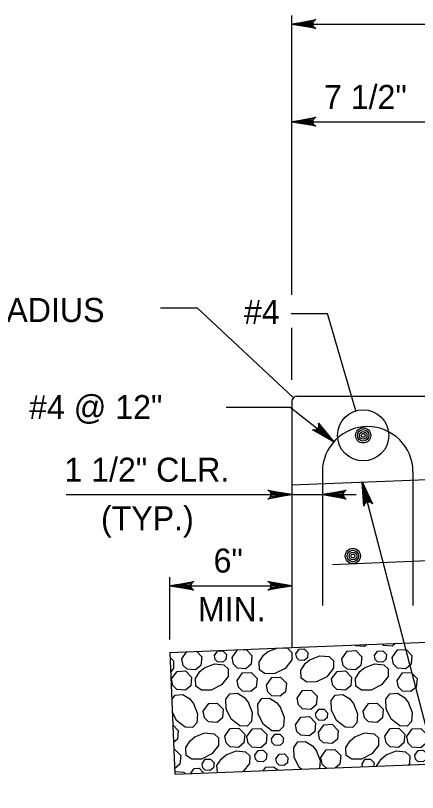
# Model space of a CAD drawing. Extents: x 2084213 to 2099800, y 976677 to 981262.
# Drawn here: x 2095066.5 to 2095231.3, y 976944.9 to 977263.3 of the extents above; entities that cross this region are included whole.
import ezdxf

# ---------------------------------------------------------------- set-up
doc = ezdxf.new("R2010")
doc.units = 0
doc.layers.add('1', color=7, linetype='Continuous')

msp = doc.modelspace()

# ---------------------------------------------------------------- linework, layer by layer
at = {"layer": '1'}
for p, q in [((2095179.78, 977148.81), (2095179.78, 977263.26)), ((2095179.78, 977259.75), (2095246.45, 977259.75)), ((2095179.78, 977219.75), (2095293.16, 977219.75)), ((2095126, 977143.47), (2095140.93, 977143.47)), ((2095180.39, 977106.67), (2095140.93, 977143.47)), ((2095179.48, 977141.19), (2095194.42, 977141.19)), ((2095206.05, 977101.32), (2095194.42, 977141.19)), ((2095179.78, 977114.01), (2095179.78, 977135.31)), ((2095181.86, 977107.28), (2095236.37, 977107.28)), ((2095179.78, 977105.2), (2095179.78, 977004.35)), ((2095152.83, 977102.87), (2095178.95, 977102.87)), ((2095196.94, 977088.58), (2095178.95, 977102.87)), ((2095209, 977091.25), (2095209, 977091.25)), ((2095192.28, 977076.28), (2095192.28, 977021.52)), ((2095229.4, 977076.27), (2095229.4, 977021.51)), ((2095179.78, 977071), (2095246.45, 977073.67)), ((2095244.96, 976932.65), (2095208.54, 977072.16)), ((2095087.34, 977067.01), (2095206.14, 977067.01)), ((2095196.45, 977038.38), (2095404.32, 977046.69)), ((2095129.82, 977007.59), (2095129.82, 977033.16)), ((2095129.82, 977029.61), (2095179.78, 977029.61)), ((2095179.78, 977004.35), (2095404.32, 977013.33)), ((2095129.82, 977002.35), (2095179.78, 977004.35)), ((2095129.82, 977002.35), (2095131.82, 976952.39)), ((2095131.82, 976952.39), (2095404.32, 976963.29))]:
    msp.add_line(p, q, dxfattribs=at)
for points in [[(2095179.78, 977259.75), (2095189.56, 977261.58), (2095189.19, 977261.32), (2095188.81, 977261.06), (2095188.62, 977260.73), (2095188.42, 977260.4), (2095188.36, 977260.07), (2095188.31, 977259.75), (2095188.36, 977259.42), (2095188.42, 977259.09), (2095188.62, 977258.76), (2095188.81, 977258.43), (2095189.19, 977258.17), (2095189.56, 977257.91), (2095179.78, 977259.75), (2095189.19, 977258.17), (2095188.81, 977258.43), (2095179.78, 977259.75), (2095188.62, 977258.76), (2095188.42, 977259.09), (2095179.78, 977259.75), (2095188.36, 977259.42), (2095188.31, 977259.75), (2095179.78, 977259.75), (2095188.36, 977260.07), (2095188.42, 977260.4), (2095179.78, 977259.75), (2095188.62, 977260.73), (2095188.81, 977261.06), (2095179.78, 977259.75), (2095189.19, 977261.32)], [(2095179.78, 977219.75), (2095189.56, 977221.58), (2095189.19, 977221.32), (2095188.81, 977221.06), (2095188.62, 977220.73), (2095188.42, 977220.4), (2095188.36, 977220.07), (2095188.31, 977219.75), (2095188.36, 977219.42), (2095188.42, 977219.09), (2095188.62, 977218.76), (2095188.81, 977218.43), (2095189.19, 977218.17), (2095189.56, 977217.91), (2095179.78, 977219.75), (2095189.19, 977218.17), (2095188.81, 977218.43), (2095179.78, 977219.75), (2095188.62, 977218.76), (2095188.42, 977219.09), (2095179.78, 977219.75), (2095188.36, 977219.42), (2095188.31, 977219.75), (2095179.78, 977219.75), (2095188.36, 977220.07), (2095188.42, 977220.4), (2095179.78, 977219.75), (2095188.62, 977220.73), (2095188.81, 977221.06), (2095179.78, 977219.75), (2095189.19, 977221.32)], [(2095196.94, 977088.58), (2095188.29, 977093.5), (2095188.74, 977093.46), (2095189.2, 977093.41), (2095189.56, 977093.54), (2095189.92, 977093.66), (2095190.17, 977093.88), (2095190.43, 977094.09), (2095190.6, 977094.38), (2095190.77, 977094.67), (2095190.83, 977095.04), (2095190.89, 977095.42), (2095190.77, 977095.86), (2095190.65, 977096.3), (2095196.94, 977088.58), (2095190.77, 977095.86), (2095190.89, 977095.42), (2095196.94, 977088.58), (2095190.83, 977095.04), (2095190.77, 977094.67), (2095196.94, 977088.58), (2095190.6, 977094.38), (2095190.43, 977094.09), (2095196.94, 977088.58), (2095190.17, 977093.88), (2095189.92, 977093.66), (2095196.94, 977088.58), (2095189.56, 977093.54), (2095189.2, 977093.41), (2095196.94, 977088.58), (2095188.74, 977093.46)], [(2095208.54, 977072.16), (2095212.79, 977063.15), (2095212.44, 977063.45), (2095212.09, 977063.75), (2095211.72, 977063.85), (2095211.36, 977063.96), (2095211.03, 977063.93), (2095210.69, 977063.9), (2095210.39, 977063.76), (2095210.09, 977063.63), (2095209.82, 977063.36), (2095209.55, 977063.09), (2095209.39, 977062.65), (2095209.24, 977062.22), (2095208.54, 977072.16), (2095209.39, 977062.65), (2095209.55, 977063.09), (2095208.54, 977072.16), (2095209.82, 977063.36), (2095210.09, 977063.63), (2095208.54, 977072.16), (2095210.39, 977063.76), (2095210.69, 977063.9), (2095208.54, 977072.16), (2095211.03, 977063.93), (2095211.36, 977063.96), (2095208.54, 977072.16), (2095211.72, 977063.85), (2095212.09, 977063.75), (2095208.54, 977072.16), (2095212.44, 977063.45)], [(2095179.78, 977067.01), (2095169.99, 977065.17), (2095170.37, 977065.43), (2095170.75, 977065.7), (2095170.94, 977066.02), (2095171.14, 977066.35), (2095171.19, 977066.68), (2095171.25, 977067.01), (2095171.19, 977067.34), (2095171.14, 977067.66), (2095170.94, 977067.99), (2095170.75, 977068.32), (2095170.37, 977068.58), (2095169.99, 977068.84), (2095179.78, 977067.01), (2095170.37, 977068.58), (2095170.75, 977068.32), (2095179.78, 977067.01), (2095170.94, 977067.99), (2095171.14, 977067.66), (2095179.78, 977067.01), (2095171.19, 977067.34), (2095171.25, 977067.01), (2095179.78, 977067.01), (2095171.19, 977066.68), (2095171.14, 977066.35), (2095179.78, 977067.01), (2095170.94, 977066.02), (2095170.75, 977065.7), (2095179.78, 977067.01), (2095170.37, 977065.43)], [(2095192.28, 977067.01), (2095202.06, 977068.84), (2095201.69, 977068.58), (2095201.31, 977068.32), (2095201.12, 977067.99), (2095200.92, 977067.66), (2095200.86, 977067.34), (2095200.81, 977067.01), (2095200.86, 977066.68), (2095200.92, 977066.35), (2095201.12, 977066.02), (2095201.31, 977065.7), (2095201.69, 977065.43), (2095202.06, 977065.17), (2095192.28, 977067.01), (2095201.69, 977065.43), (2095201.31, 977065.7), (2095192.28, 977067.01), (2095201.12, 977066.02), (2095200.92, 977066.35), (2095192.28, 977067.01), (2095200.86, 977066.68), (2095200.81, 977067.01), (2095192.28, 977067.01), (2095200.86, 977067.34), (2095200.92, 977067.66), (2095192.28, 977067.01), (2095201.12, 977067.99), (2095201.31, 977068.32), (2095192.28, 977067.01), (2095201.69, 977068.58)], [(2095129.82, 977029.61), (2095139.6, 977031.44), (2095139.23, 977031.18), (2095138.85, 977030.92), (2095138.66, 977030.59), (2095138.46, 977030.26), (2095138.4, 977029.93), (2095138.35, 977029.61), (2095138.4, 977029.28), (2095138.46, 977028.95), (2095138.66, 977028.62), (2095138.85, 977028.29), (2095139.23, 977028.03), (2095139.6, 977027.77), (2095129.82, 977029.61), (2095139.23, 977028.03), (2095138.85, 977028.29), (2095129.82, 977029.61), (2095138.66, 977028.62), (2095138.46, 977028.95), (2095129.82, 977029.61), (2095138.4, 977029.28), (2095138.35, 977029.61), (2095129.82, 977029.61), (2095138.4, 977029.93), (2095138.46, 977030.26), (2095129.82, 977029.61), (2095138.66, 977030.59), (2095138.85, 977030.92), (2095129.82, 977029.61), (2095139.23, 977031.18)], [(2095179.78, 977029.61), (2095169.99, 977027.77), (2095170.37, 977028.03), (2095170.75, 977028.29), (2095170.94, 977028.62), (2095171.14, 977028.95), (2095171.19, 977029.28), (2095171.25, 977029.61), (2095171.19, 977029.93), (2095171.14, 977030.26), (2095170.94, 977030.59), (2095170.75, 977030.92), (2095170.37, 977031.18), (2095169.99, 977031.44), (2095179.78, 977029.61), (2095170.37, 977031.18), (2095170.75, 977030.92), (2095179.78, 977029.61), (2095170.94, 977030.59), (2095171.14, 977030.26), (2095179.78, 977029.61), (2095171.19, 977029.93), (2095171.25, 977029.61), (2095179.78, 977029.61), (2095171.19, 977029.28), (2095171.14, 977028.95), (2095179.78, 977029.61), (2095170.94, 977028.62), (2095170.75, 977028.29), (2095179.78, 977029.61), (2095170.37, 977028.03)], [(2095210.51, 977005.58), (2095209.49, 977004.73), (2095206.01, 977004.98), (2095205.6, 977005.38)], [(2095222.3, 977006.05), (2095220.87, 977004.86), (2095217.39, 977005.11), (2095216.66, 977005.83)], [(2095140.65, 977002.79), (2095142.82, 977000.53), (2095142.47, 976996.97), (2095140.3, 976995.17), (2095136.82, 976995.42), (2095135.18, 976997), (2095134.65, 976999.73)], [(2095134.65, 976999.73), (2095136.69, 977002.63)], [(2095148.03, 977001.02), (2095149.36, 977002.9), (2095151.47, 977003.02), (2095152.94, 977001.5), (2095152.72, 976999.37), (2095151.42, 976998.28), (2095149.33, 976998.43), (2095148.35, 976999.38), (2095148.03, 977001.02)], [(2095155.26, 977000.21), (2095157.47, 977003.35), (2095160.99, 977003.55), (2095163.43, 977001.01), (2095163.08, 976997.45), (2095160.91, 976995.64), (2095157.43, 976995.89), (2095155.79, 976997.48), (2095155.26, 977000.21)], [(2095175.96, 977004.2), (2095177.98, 977004.03), (2095179.78, 977002.31), (2095179.72, 976999.24), (2095176.99, 976995.74), (2095172.76, 976993.63), (2095168.78, 976993.56), (2095166.54, 976995.15), (2095166.33, 976998.32), (2095168.14, 977001.16), (2095170.23, 977002.82)], [(2095170.06, 977002.72), (2095173.56, 977004.1)], [(2095181.45, 977001.75), (2095182.77, 977003.63), (2095184.88, 977003.75), (2095186.35, 977002.23), (2095186.14, 977000.09), (2095184.83, 976999.01), (2095182.75, 976999.16), (2095181.76, 977000.11), (2095181.45, 977001.75)], [(2095200.23, 976999.73), (2095202.43, 977002.87), (2095205.95, 977003.07), (2095208.4, 977000.53), (2095208.05, 976996.97), (2095205.87, 976995.17), (2095202.4, 976995.42), (2095200.76, 976997), (2095200.23, 976999.73)], [(2095213.61, 977001.02), (2095214.93, 977002.9), (2095217.05, 977003.02), (2095218.52, 977001.5), (2095218.3, 976999.37), (2095217, 976998.28), (2095214.91, 976998.43), (2095213.93, 976999.38), (2095213.61, 977001.02)], [(2095220.84, 977000.21), (2095223.04, 977003.35), (2095226.57, 977003.55), (2095229.01, 977001.01), (2095228.66, 976997.45), (2095226.48, 976995.64), (2095223.01, 976995.89), (2095221.37, 976997.48), (2095220.84, 977000.21)], [(2095129.9, 977000.25), (2095131.3, 976998.93), (2095131.24, 976995.85), (2095130.14, 976994.43)], [(2095187.16, 976999.33), (2095191.29, 977000.96), (2095195.08, 977000.64), (2095196.88, 976998.93), (2095196.82, 976995.85), (2095194.09, 976992.35), (2095189.86, 976990.24), (2095185.88, 976990.17), (2095183.64, 976991.76), (2095183.42, 976994.94), (2095185.24, 976997.77), (2095187.33, 976999.44)], [(2095144, 976995.99), (2095148.12, 976997.63), (2095151.91, 976997.3), (2095153.72, 976995.59), (2095153.66, 976992.51), (2095150.92, 976989.02), (2095146.7, 976986.91), (2095142.72, 976986.84), (2095140.47, 976988.43), (2095140.26, 976991.6), (2095142.08, 976994.44), (2095144.16, 976996.1)], [(2095209.58, 976995.99), (2095213.7, 976997.63), (2095217.49, 976997.3), (2095219.29, 976995.59), (2095219.24, 976992.51), (2095216.5, 976989.02), (2095212.28, 976986.91), (2095208.3, 976986.84), (2095206.05, 976988.43), (2095205.84, 976991.6), (2095207.66, 976994.44), (2095209.74, 976996.1)], [(2095130.5, 976991.43), (2095132.7, 976994.57), (2095136.23, 976994.77), (2095138.67, 976992.23), (2095138.32, 976988.67), (2095136.14, 976986.86), (2095132.67, 976987.12), (2095131.03, 976988.7), (2095130.5, 976991.43)], [(2095157.34, 976990.81), (2095159.54, 976993.95), (2095163.06, 976994.15), (2095165.51, 976991.62), (2095165.16, 976988.06), (2095162.98, 976986.25), (2095159.5, 976986.5), (2095157.87, 976988.09), (2095157.34, 976990.81)], [(2095169.39, 976988.89), (2095171.6, 976992.03), (2095175.12, 976992.23), (2095177.57, 976989.69), (2095177.21, 976986.14), (2095175.04, 976984.33), (2095171.56, 976984.58), (2095169.93, 976986.17), (2095169.4, 976988.89)], [(2095196.08, 976991.43), (2095198.28, 976994.57), (2095201.8, 976994.77), (2095204.25, 976992.23), (2095203.9, 976988.67), (2095201.72, 976986.86), (2095198.25, 976987.12), (2095196.61, 976988.7), (2095196.08, 976991.43)], [(2095222.91, 976990.81), (2095225.12, 976993.95), (2095228.64, 976994.15), (2095231.09, 976991.62), (2095230.73, 976988.06), (2095228.56, 976986.25), (2095225.08, 976986.5), (2095223.45, 976988.09), (2095222.92, 976990.81)], [(2095181.93, 976983.56), (2095184.14, 976986.7), (2095187.66, 976986.9), (2095190.11, 976984.36), (2095189.76, 976980.8), (2095187.58, 976978.99), (2095184.1, 976979.24), (2095182.47, 976980.83), (2095181.94, 976983.56)], [(2095130.59, 976982.97), (2095131.94, 976984.87), (2095135.12, 976985.08), (2095137.95, 976983.26), (2095139.61, 976981.18)], [(2095161.93, 976981.88), (2095163.56, 976977.75), (2095163.23, 976973.96), (2095161.52, 976972.16), (2095158.44, 976972.22), (2095154.95, 976974.95), (2095152.84, 976979.18), (2095152.77, 976983.16), (2095154.36, 976985.4), (2095157.53, 976985.61), (2095160.37, 976983.79), (2095162.03, 976981.71)], [(2095175, 976979.87), (2095176.64, 976975.75), (2095176.31, 976971.96), (2095174.6, 976970.16), (2095171.52, 976970.21), (2095168.03, 976972.95), (2095165.92, 976977.17), (2095165.84, 976981.16), (2095167.44, 976983.4), (2095170.61, 976983.61), (2095173.45, 976981.79), (2095175.11, 976979.71)], [(2095205.09, 976981.34), (2095206.72, 976977.22), (2095206.4, 976973.43), (2095204.68, 976971.62), (2095201.61, 976971.68), (2095198.11, 976974.42), (2095196, 976978.64), (2095195.93, 976982.62), (2095197.52, 976984.87), (2095200.7, 976985.08), (2095203.53, 976983.26), (2095205.19, 976981.18)], [(2095227.5, 976981.88), (2095229.14, 976977.75), (2095228.81, 976973.96), (2095227.1, 976972.16), (2095224.02, 976972.22), (2095220.53, 976974.95), (2095218.42, 976979.18), (2095218.35, 976983.16), (2095219.94, 976985.4), (2095223.11, 976985.61), (2095225.95, 976983.79), (2095227.61, 976981.71)], [(2095139.51, 976981.34), (2095141.14, 976977.22), (2095140.82, 976973.43), (2095139.1, 976971.62), (2095136.03, 976971.68), (2095132.53, 976974.42), (2095130.8, 976977.89)], [(2095143.47, 976978.22), (2095145.68, 976981.36), (2095149.2, 976981.56), (2095151.65, 976979.02), (2095151.29, 976975.47), (2095149.12, 976973.66), (2095145.64, 976973.91), (2095144, 976975.49), (2095143.47, 976978.22)], [(2095209.05, 976978.22), (2095211.25, 976981.36), (2095214.78, 976981.56), (2095217.23, 976979.02), (2095216.87, 976975.47), (2095214.7, 976973.66), (2095211.22, 976973.91), (2095209.58, 976975.49), (2095209.05, 976978.22)], [(2095189.51, 976977.13), (2095190.84, 976979.01), (2095192.95, 976979.13), (2095194.42, 976977.61), (2095194.21, 976975.48), (2095192.9, 976974.39), (2095190.81, 976974.54), (2095189.83, 976975.49), (2095189.51, 976977.13)], [(2095181.32, 976972.66), (2095183.52, 976975.8), (2095187.04, 976976), (2095189.49, 976973.46), (2095189.14, 976969.91), (2095186.96, 976968.1), (2095183.48, 976968.35), (2095181.85, 976969.94), (2095181.32, 976972.66)], [(2095131.01, 976972.66), (2095133.23, 976970.35), (2095132.88, 976966.79), (2095131.29, 976965.47)], [(2095152.3, 976967.99), (2095154.5, 976971.13), (2095158.02, 976971.33), (2095160.47, 976968.79), (2095160.12, 976965.24), (2095157.94, 976963.43), (2095154.47, 976963.68), (2095152.83, 976965.27), (2095152.3, 976967.99)], [(2095161.37, 976967.86), (2095163.58, 976971), (2095167.1, 976971.2), (2095169.55, 976968.66), (2095169.19, 976965.1), (2095167.02, 976963.29), (2095163.54, 976963.55), (2095161.9, 976965.13), (2095161.37, 976967.86)], [(2095190.64, 976969.55), (2095192.84, 976972.68), (2095196.36, 976972.89), (2095198.81, 976970.35), (2095198.46, 976966.79), (2095196.28, 976964.98), (2095192.8, 976965.23), (2095191.17, 976966.82), (2095190.64, 976969.55)], [(2095217.88, 976967.99), (2095220.08, 976971.13), (2095223.6, 976971.33), (2095226.05, 976968.79), (2095225.7, 976965.24), (2095223.52, 976963.43), (2095220.05, 976963.68), (2095218.41, 976965.27), (2095217.88, 976967.99)], [(2095226.95, 976967.86), (2095229.15, 976971), (2095232.68, 976971.2), (2095235.13, 976968.66), (2095234.77, 976965.1), (2095232.59, 976963.29), (2095229.12, 976963.55), (2095227.48, 976965.13), (2095226.95, 976967.86)], [(2095139.99, 976967.71), (2095144.12, 976969.34), (2095147.91, 976969.01), (2095149.71, 976967.3), (2095149.66, 976964.23), (2095146.92, 976960.73), (2095142.7, 976958.62), (2095138.71, 976958.55), (2095136.47, 976960.14), (2095136.26, 976963.31), (2095138.08, 976966.15), (2095140.16, 976967.81)], [(2095171.41, 976966.89), (2095172.73, 976968.77), (2095174.84, 976968.89), (2095176.31, 976967.37), (2095176.1, 976965.24), (2095174.79, 976964.15), (2095172.71, 976964.3), (2095171.73, 976965.25), (2095171.41, 976966.89)], [(2095205.57, 976967.71), (2095209.7, 976969.34), (2095213.49, 976969.01), (2095215.29, 976967.3), (2095215.23, 976964.23), (2095212.5, 976960.73), (2095208.27, 976958.62), (2095204.29, 976958.55), (2095202.05, 976960.14), (2095201.84, 976963.31), (2095203.66, 976966.15), (2095205.74, 976967.81)], [(2095183.71, 976954.47), (2095182.77, 976955.2), (2095180.66, 976959.43), (2095180.59, 976963.41), (2095182.18, 976965.65), (2095185.35, 976965.86), (2095188.19, 976964.04), (2095189.85, 976961.96)], [(2095131.41, 976962.54), (2095131.77, 976962.56), (2095134.21, 976960.03), (2095133.86, 976956.47), (2095131.72, 976954.69)], [(2095149.25, 976953.09), (2095149.06, 976955.94), (2095150.88, 976958.78), (2095152.96, 976960.44)], [(2095152.8, 976960.34), (2095156.92, 976961.97), (2095160.71, 976961.64), (2095162.51, 976959.93), (2095162.46, 976956.85), (2095159.84, 976953.51)], [(2095164.58, 976960.27), (2095165.9, 976962.15), (2095168.02, 976962.27), (2095169.48, 976960.75), (2095169.27, 976958.62), (2095167.97, 976957.53), (2095165.88, 976957.68), (2095164.9, 976958.63), (2095164.58, 976960.27)], [(2095173.27, 976958.72), (2095174.59, 976960.6), (2095176.7, 976960.72), (2095178.17, 976959.2), (2095177.96, 976957.07), (2095176.66, 976955.98), (2095174.57, 976956.13), (2095173.59, 976957.08), (2095173.27, 976958.72)], [(2095189.74, 976962.13), (2095191.38, 976958), (2095191.1, 976954.76)], [(2095191.62, 976959.23), (2095193.82, 976962.36), (2095197.35, 976962.56), (2095199.79, 976960.03), (2095199.44, 976956.47), (2095197.71, 976955.03)], [(2095214.66, 976955.71), (2095214.64, 976955.94), (2095216.46, 976958.78), (2095218.54, 976960.44)], [(2095218.37, 976960.34), (2095222.5, 976961.97), (2095226.29, 976961.64), (2095228.09, 976959.93), (2095228.04, 976956.85), (2095227.54, 976956.22)], [(2095230.16, 976960.27), (2095231.48, 976962.15), (2095233.6, 976962.27), (2095235.06, 976960.75), (2095234.85, 976958.62), (2095233.55, 976957.53), (2095231.46, 976957.68), (2095230.48, 976958.63), (2095230.16, 976960.27)], [(2095142.96, 976956.65), (2095144.29, 976958.53), (2095146.4, 976958.65), (2095147.87, 976957.13), (2095147.66, 976955), (2095146.35, 976953.91), (2095144.26, 976954.06), (2095143.28, 976955.01), (2095142.97, 976956.65)], [(2095194.13, 976954.89), (2095193.79, 976954.91), (2095192.15, 976956.5), (2095191.62, 976959.23)], [(2095208.54, 976956.65), (2095209.87, 976958.53), (2095211.98, 976958.65), (2095213.45, 976957.13), (2095213.3, 976955.65)], [(2095138.41, 976952.82), (2095139.74, 976954.71), (2095141.85, 976954.83), (2095143.32, 976953.31), (2095143.27, 976952.85)], [(2095168.04, 976953.84), (2095169.04, 976955.24), (2095172.21, 976955.46), (2095174.33, 976954.09)], [(2095208.77, 976955.47), (2095208.54, 976956.65)], [(2095131.77, 976953.56), (2095135.5, 976953.24), (2095136.2, 976952.57)], [(2095138.45, 976952.66), (2095138.42, 976952.82)]]:
    msp.add_lwpolyline(points, dxfattribs=at)
for centre, radius in [((2095209, 977091.25), 10.5), ((2095209, 977091.25), 3.12), ((2095209, 977091.25), 2.34), ((2095209, 977091.25), 1.56), ((2095209, 977091.25), 0.781), ((2095204.78, 977041.83), 3.12), ((2095204.78, 977041.83), 2.34), ((2095204.78, 977041.83), 1.56), ((2095204.78, 977041.83), 0.781)]:
    msp.add_circle(centre, radius, dxfattribs=at)
for centre, radius, start, end in [((2095181.86, 977105.2), 2.08, 90, 180), ((2095210.84, 977076.28), 18.56, 359.9821, 179.9821)]:
    msp.add_arc(centre, radius, start, end, dxfattribs=at)

# ---------------------------------------------------------------- texts
for s, height, p in [('7 1/2"', 9.843, (2095192.94, 977224.97)), ('1/4" RADIUS', 9.8425, (2095026.62, 977137.7)), ('#4', 9.843, (2095160.14, 977136.88)), ('#4 @ 12"', 9.843, (2095072.08, 977097.91)), ('1 1/2" CLR.', 9.8425, (2095086.55, 977072.26)), ('(TYP.)', 9.843, (2095101.55, 977052.34)), ('6"', 9.843, (2095147.69, 977035.04)), ('MIN.', 9.843, (2095141.26, 977015.12))]:
    msp.add_text(s, height=height, dxfattribs=at).set_placement(p)

doc.saveas('drawing.dxf')
